// Mitsubishi GX Works2 project: 13.5台电机顺起逆停   PLC: FX3U/FX3UC

PROGRAM MAIN
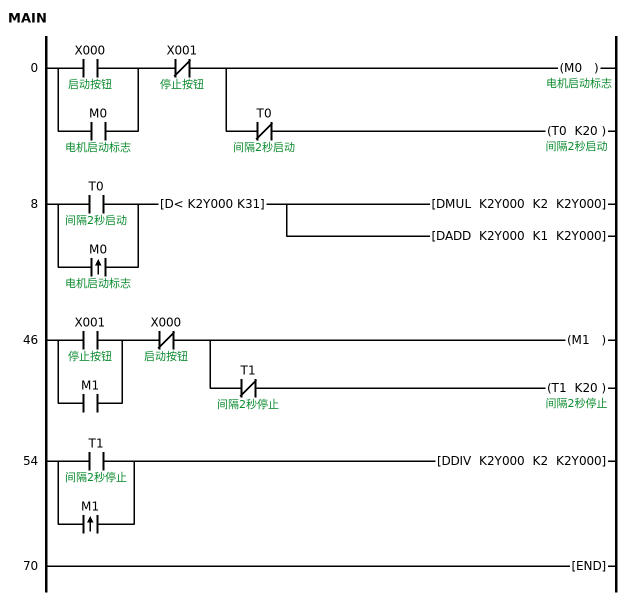
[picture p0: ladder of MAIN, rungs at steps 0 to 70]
0     LD      X000  ; 启动按钮
      OR      M0  ; 电机启动标志
      ANI     X001  ; 停止按钮
      OUT     M0  ; 电机启动标志
      ANI     T0  ; 间隔2秒启动
      OUT     T0 K20  ; 间隔2秒启动
8     LD      T0  ; 间隔2秒启动
      ORP     M0  ; 电机启动标志
      ANDD<   K2Y000 K31  ; 电机1-电机5
      DMUL    K2Y000 K2 K2Y000
      DADD    K2Y000 K1 K2Y000
46    LD      X001  ; 停止按钮
      OR      M1
      ANI     X000  ; 启动按钮
      OUT     M1
      ANI     T1  ; 间隔2秒停止
      OUT     T1 K20  ; 间隔2秒停止
54    LD      T1  ; 间隔2秒停止
      ORP     M1
      DDIV    K2Y000 K2 K2Y000
70    END
END_PROGRAM

// device comments not shown above
Y001  ; 电机2
Y002  ; 电机3
Y003  ; 电机4
Y004  ; 电机5
